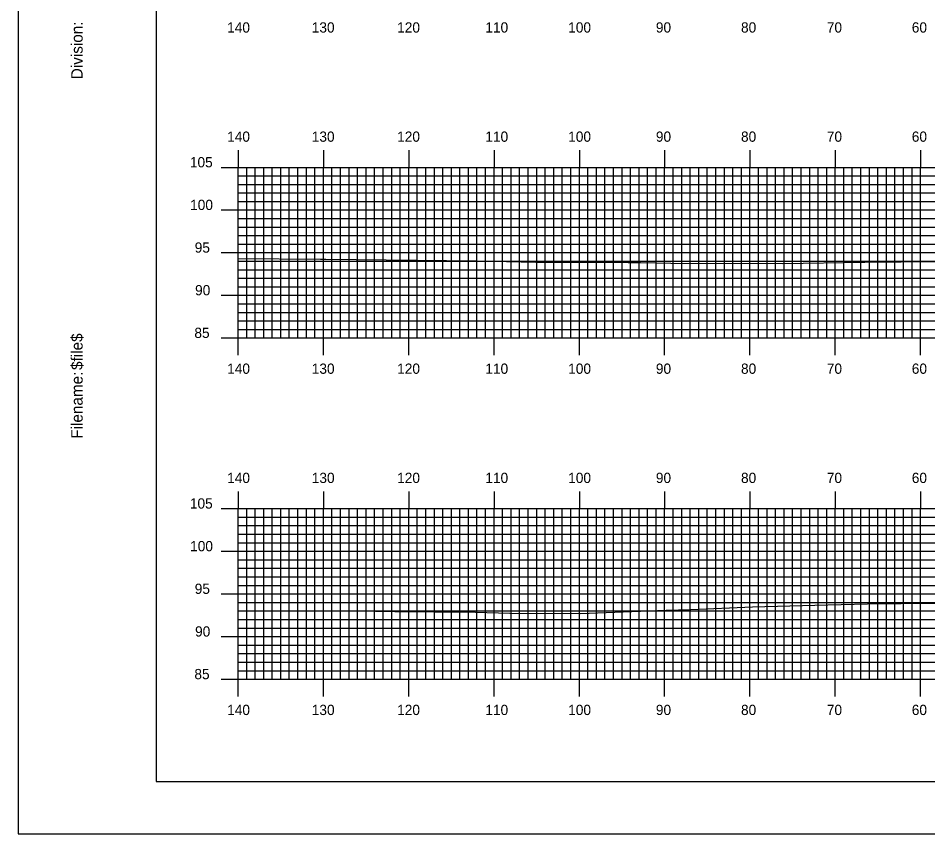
# Model space of a CAD drawing. Extents: x 1764152 to 1764495, y 442591 to 442811.
# Drawn here: x 1764152 to 1764258.7, y 442590.5 to 442686.2 of the extents above; entities that cross this region are included whole.
import ezdxf

# ---------------------------------------------------------------- set-up
doc = ezdxf.new("R2010")
doc.units = 0
for name, color, linetype in [('BORDER', 7, 'Continuous'), ('H_V ANNOTATION', 7, 'Continuous'), ('MAJOR', 7, 'Continuous'), ('MINOR', 7, 'Continuous'), ('PLOT BOUNDARY', 7, 'Continuous'), ('S_Roadway_Centerline', 7, 'Continuous')]:
    doc.layers.add(name, color=color, linetype=linetype)

msp = doc.modelspace()

# ---------------------------------------------------------------- linework, layer by layer
at = {"layer": 'BORDER'}
msp.add_lwpolyline([(1764168.23, 442596.67), (1764488.23, 442596.67), (1764488.23, 442806.67), (1764168.23, 442806.67)], close=True, dxfattribs=at)
at = {"layer": 'MAJOR'}
for p, q in [((1764177.83, 442670.67), (1764177.83, 442668.67)), ((1764187.83, 442670.67), (1764187.83, 442668.67)), ((1764197.83, 442670.67), (1764197.83, 442668.67)), ((1764207.83, 442670.67), (1764207.83, 442668.67)), ((1764217.83, 442670.67), (1764217.83, 442668.67)), ((1764227.83, 442670.67), (1764227.83, 442668.67)), ((1764237.83, 442670.67), (1764237.83, 442668.67)), ((1764247.83, 442670.67), (1764247.83, 442668.67)), ((1764257.83, 442670.67), (1764257.83, 442668.67)), ((1764175.83, 442668.67), (1764177.83, 442668.67)), ((1764177.83, 442668.67), (1764457.83, 442668.67)), ((1764177.83, 442648.67), (1764177.83, 442668.67)), ((1764177.83, 442648.67), (1764177.83, 442668.67)), ((1764177.83, 442668.67), (1764457.83, 442668.67)), ((1764187.83, 442648.67), (1764187.83, 442668.67)), ((1764197.83, 442648.67), (1764197.83, 442668.67)), ((1764207.83, 442648.67), (1764207.83, 442668.67)), ((1764217.83, 442648.67), (1764217.83, 442668.67)), ((1764227.83, 442648.67), (1764227.83, 442668.67)), ((1764237.83, 442648.67), (1764237.83, 442668.67)), ((1764247.83, 442648.67), (1764247.83, 442668.67)), ((1764257.83, 442648.67), (1764257.83, 442668.67)), ((1764175.83, 442663.67), (1764177.83, 442663.67)), ((1764177.83, 442663.67), (1764457.83, 442663.67)), ((1764175.83, 442658.67), (1764177.83, 442658.67)), ((1764177.83, 442658.67), (1764457.83, 442658.67)), ((1764175.83, 442653.67), (1764177.83, 442653.67)), ((1764177.83, 442653.67), (1764457.83, 442653.67)), ((1764175.83, 442648.67), (1764177.83, 442648.67)), ((1764177.83, 442648.67), (1764457.83, 442648.67)), ((1764177.83, 442648.67), (1764457.83, 442648.67)), ((1764177.83, 442646.66), (1764177.83, 442648.67)), ((1764187.83, 442646.66), (1764187.83, 442648.67)), ((1764197.83, 442646.66), (1764197.83, 442648.67)), ((1764207.83, 442646.66), (1764207.83, 442648.67)), ((1764217.83, 442646.66), (1764217.83, 442648.67)), ((1764227.83, 442646.66), (1764227.83, 442648.67)), ((1764237.83, 442646.66), (1764237.83, 442648.67)), ((1764247.83, 442646.66), (1764247.83, 442648.67)), ((1764257.83, 442646.66), (1764257.83, 442648.67)), ((1764177.83, 442630.67), (1764177.83, 442628.67)), ((1764187.83, 442630.67), (1764187.83, 442628.67)), ((1764197.83, 442630.67), (1764197.83, 442628.67)), ((1764207.83, 442630.67), (1764207.83, 442628.67)), ((1764217.83, 442630.67), (1764217.83, 442628.67)), ((1764227.83, 442630.67), (1764227.83, 442628.67)), ((1764237.83, 442630.67), (1764237.83, 442628.67)), ((1764247.83, 442630.67), (1764247.83, 442628.67)), ((1764257.83, 442630.67), (1764257.83, 442628.67)), ((1764175.83, 442628.67), (1764177.83, 442628.67)), ((1764177.83, 442628.67), (1764457.83, 442628.67)), ((1764177.83, 442608.67), (1764177.83, 442628.67)), ((1764177.83, 442608.67), (1764177.83, 442628.67)), ((1764177.83, 442628.67), (1764457.83, 442628.67)), ((1764187.83, 442608.67), (1764187.83, 442628.67)), ((1764197.83, 442608.67), (1764197.83, 442628.67)), ((1764207.83, 442608.67), (1764207.83, 442628.67)), ((1764217.83, 442608.67), (1764217.83, 442628.67)), ((1764227.83, 442608.67), (1764227.83, 442628.67)), ((1764237.83, 442608.67), (1764237.83, 442628.67)), ((1764247.83, 442608.67), (1764247.83, 442628.67)), ((1764257.83, 442608.67), (1764257.83, 442628.67)), ((1764175.83, 442623.67), (1764177.83, 442623.67)), ((1764177.83, 442623.67), (1764457.83, 442623.67)), ((1764175.83, 442618.67), (1764177.83, 442618.67)), ((1764177.83, 442618.67), (1764457.83, 442618.67)), ((1764175.83, 442613.67), (1764177.83, 442613.67)), ((1764177.83, 442613.67), (1764457.83, 442613.67)), ((1764175.83, 442608.67), (1764177.83, 442608.67)), ((1764177.83, 442608.67), (1764457.83, 442608.67)), ((1764177.83, 442608.67), (1764457.83, 442608.67)), ((1764177.83, 442606.66), (1764177.83, 442608.67)), ((1764187.83, 442606.66), (1764187.83, 442608.67)), ((1764197.83, 442606.66), (1764197.83, 442608.67)), ((1764207.83, 442606.66), (1764207.83, 442608.67)), ((1764217.83, 442606.66), (1764217.83, 442608.67)), ((1764227.83, 442606.66), (1764227.83, 442608.67)), ((1764237.83, 442606.66), (1764237.83, 442608.67)), ((1764247.83, 442606.66), (1764247.83, 442608.67)), ((1764257.83, 442606.66), (1764257.83, 442608.67))]:
    msp.add_line(p, q, dxfattribs=at)
at = {"layer": 'MINOR'}
for p, q in [((1764178.83, 442648.67), (1764178.83, 442668.67)), ((1764179.83, 442648.67), (1764179.83, 442668.67)), ((1764180.83, 442648.67), (1764180.83, 442668.67)), ((1764181.83, 442648.67), (1764181.83, 442668.67)), ((1764182.83, 442648.67), (1764182.83, 442668.67)), ((1764183.83, 442648.67), (1764183.83, 442668.67)), ((1764184.83, 442648.67), (1764184.83, 442668.67)), ((1764185.83, 442648.67), (1764185.83, 442668.67)), ((1764186.83, 442648.67), (1764186.83, 442668.67)), ((1764188.83, 442648.67), (1764188.83, 442668.67)), ((1764189.83, 442648.67), (1764189.83, 442668.67)), ((1764190.83, 442648.67), (1764190.83, 442668.67)), ((1764191.83, 442648.67), (1764191.83, 442668.67)), ((1764192.83, 442648.67), (1764192.83, 442668.67)), ((1764193.83, 442648.67), (1764193.83, 442668.67)), ((1764194.83, 442648.67), (1764194.83, 442668.67)), ((1764195.83, 442648.67), (1764195.83, 442668.67)), ((1764196.83, 442648.67), (1764196.83, 442668.67)), ((1764198.83, 442648.67), (1764198.83, 442668.67)), ((1764199.83, 442648.67), (1764199.83, 442668.67)), ((1764200.83, 442648.67), (1764200.83, 442668.67)), ((1764201.83, 442648.67), (1764201.83, 442668.67)), ((1764202.83, 442648.67), (1764202.83, 442668.67)), ((1764203.83, 442648.67), (1764203.83, 442668.67)), ((1764204.83, 442648.67), (1764204.83, 442668.67)), ((1764205.83, 442648.67), (1764205.83, 442668.67)), ((1764206.83, 442648.67), (1764206.83, 442668.67)), ((1764208.83, 442648.67), (1764208.83, 442668.67)), ((1764209.83, 442648.67), (1764209.83, 442668.67)), ((1764210.83, 442648.67), (1764210.83, 442668.67)), ((1764211.83, 442648.67), (1764211.83, 442668.67)), ((1764212.83, 442648.67), (1764212.83, 442668.67)), ((1764213.83, 442648.67), (1764213.83, 442668.67)), ((1764214.83, 442648.67), (1764214.83, 442668.67)), ((1764215.83, 442648.67), (1764215.83, 442668.67)), ((1764216.83, 442648.67), (1764216.83, 442668.67)), ((1764218.83, 442648.67), (1764218.83, 442668.67)), ((1764219.83, 442648.67), (1764219.83, 442668.67)), ((1764220.83, 442648.67), (1764220.83, 442668.67)), ((1764221.83, 442648.67), (1764221.83, 442668.67)), ((1764222.83, 442648.67), (1764222.83, 442668.67)), ((1764223.83, 442648.67), (1764223.83, 442668.67)), ((1764224.83, 442648.67), (1764224.83, 442668.67)), ((1764225.83, 442648.67), (1764225.83, 442668.67)), ((1764226.83, 442648.67), (1764226.83, 442668.67)), ((1764228.83, 442648.67), (1764228.83, 442668.67)), ((1764229.83, 442648.67), (1764229.83, 442668.67)), ((1764230.83, 442648.67), (1764230.83, 442668.67)), ((1764231.83, 442648.67), (1764231.83, 442668.67)), ((1764232.83, 442648.67), (1764232.83, 442668.67)), ((1764233.83, 442648.67), (1764233.83, 442668.67)), ((1764234.83, 442648.67), (1764234.83, 442668.67)), ((1764235.83, 442648.67), (1764235.83, 442668.67)), ((1764236.83, 442648.67), (1764236.83, 442668.67)), ((1764238.83, 442648.67), (1764238.83, 442668.67)), ((1764239.83, 442648.67), (1764239.83, 442668.67)), ((1764240.83, 442648.67), (1764240.83, 442668.67)), ((1764241.83, 442648.67), (1764241.83, 442668.67)), ((1764242.83, 442648.67), (1764242.83, 442668.67)), ((1764243.83, 442648.67), (1764243.83, 442668.67)), ((1764244.83, 442648.67), (1764244.83, 442668.67)), ((1764245.83, 442648.67), (1764245.83, 442668.67)), ((1764246.83, 442648.67), (1764246.83, 442668.67)), ((1764248.83, 442648.67), (1764248.83, 442668.67)), ((1764249.83, 442648.67), (1764249.83, 442668.67)), ((1764250.83, 442648.67), (1764250.83, 442668.67)), ((1764251.83, 442648.67), (1764251.83, 442668.67)), ((1764252.83, 442648.67), (1764252.83, 442668.67)), ((1764253.83, 442648.67), (1764253.83, 442668.67)), ((1764254.83, 442648.67), (1764254.83, 442668.67)), ((1764255.83, 442648.67), (1764255.83, 442668.67)), ((1764256.83, 442648.67), (1764256.83, 442668.67)), ((1764177.83, 442667.67), (1764457.83, 442667.67)), ((1764177.83, 442667.67), (1764179.84, 442667.67)), ((1764177.83, 442666.67), (1764457.83, 442666.67)), ((1764177.83, 442666.67), (1764179.84, 442666.67)), ((1764177.83, 442665.67), (1764457.83, 442665.67)), ((1764177.83, 442665.67), (1764179.84, 442665.67)), ((1764177.83, 442664.67), (1764457.83, 442664.67)), ((1764177.83, 442664.67), (1764179.84, 442664.67)), ((1764177.83, 442662.67), (1764457.83, 442662.67)), ((1764177.83, 442662.67), (1764179.84, 442662.67)), ((1764177.83, 442661.67), (1764457.83, 442661.67)), ((1764177.83, 442661.67), (1764179.84, 442661.67)), ((1764177.83, 442660.67), (1764457.83, 442660.67)), ((1764177.83, 442660.67), (1764179.84, 442660.67)), ((1764177.83, 442659.67), (1764457.83, 442659.67)), ((1764177.83, 442659.67), (1764179.84, 442659.67)), ((1764177.83, 442657.67), (1764457.83, 442657.67)), ((1764177.83, 442657.67), (1764179.84, 442657.67)), ((1764177.83, 442656.67), (1764457.83, 442656.67)), ((1764177.83, 442656.67), (1764179.84, 442656.67)), ((1764177.83, 442655.67), (1764457.83, 442655.67)), ((1764177.83, 442655.67), (1764179.84, 442655.67)), ((1764177.83, 442654.67), (1764457.83, 442654.67)), ((1764177.83, 442654.67), (1764179.84, 442654.67)), ((1764177.83, 442652.67), (1764457.83, 442652.67)), ((1764177.83, 442652.67), (1764179.84, 442652.67)), ((1764177.83, 442651.67), (1764457.83, 442651.67)), ((1764177.83, 442651.67), (1764179.84, 442651.67)), ((1764177.83, 442650.67), (1764457.83, 442650.67)), ((1764177.83, 442650.67), (1764179.84, 442650.67)), ((1764177.83, 442649.67), (1764457.83, 442649.67)), ((1764177.83, 442649.67), (1764179.84, 442649.67)), ((1764178.83, 442608.67), (1764178.83, 442628.67)), ((1764179.83, 442608.67), (1764179.83, 442628.67)), ((1764180.83, 442608.67), (1764180.83, 442628.67)), ((1764181.83, 442608.67), (1764181.83, 442628.67)), ((1764182.83, 442608.67), (1764182.83, 442628.67)), ((1764183.83, 442608.67), (1764183.83, 442628.67)), ((1764184.83, 442608.67), (1764184.83, 442628.67)), ((1764185.83, 442608.67), (1764185.83, 442628.67)), ((1764186.83, 442608.67), (1764186.83, 442628.67)), ((1764188.83, 442608.67), (1764188.83, 442628.67)), ((1764189.83, 442608.67), (1764189.83, 442628.67)), ((1764190.83, 442608.67), (1764190.83, 442628.67)), ((1764191.83, 442608.67), (1764191.83, 442628.67)), ((1764192.83, 442608.67), (1764192.83, 442628.67)), ((1764193.83, 442608.67), (1764193.83, 442628.67)), ((1764194.83, 442608.67), (1764194.83, 442628.67)), ((1764195.83, 442608.67), (1764195.83, 442628.67)), ((1764196.83, 442608.67), (1764196.83, 442628.67)), ((1764198.83, 442608.67), (1764198.83, 442628.67)), ((1764199.83, 442608.67), (1764199.83, 442628.67)), ((1764200.83, 442608.67), (1764200.83, 442628.67)), ((1764201.83, 442608.67), (1764201.83, 442628.67)), ((1764202.83, 442608.67), (1764202.83, 442628.67)), ((1764203.83, 442608.67), (1764203.83, 442628.67)), ((1764204.83, 442608.67), (1764204.83, 442628.67)), ((1764205.83, 442608.67), (1764205.83, 442628.67)), ((1764206.83, 442608.67), (1764206.83, 442628.67)), ((1764208.83, 442608.67), (1764208.83, 442628.67)), ((1764209.83, 442608.67), (1764209.83, 442628.67)), ((1764210.83, 442608.67), (1764210.83, 442628.67)), ((1764211.83, 442608.67), (1764211.83, 442628.67)), ((1764212.83, 442608.67), (1764212.83, 442628.67)), ((1764213.83, 442608.67), (1764213.83, 442628.67)), ((1764214.83, 442608.67), (1764214.83, 442628.67)), ((1764215.83, 442608.67), (1764215.83, 442628.67)), ((1764216.83, 442608.67), (1764216.83, 442628.67)), ((1764218.83, 442608.67), (1764218.83, 442628.67)), ((1764219.83, 442608.67), (1764219.83, 442628.67)), ((1764220.83, 442608.67), (1764220.83, 442628.67)), ((1764221.83, 442608.67), (1764221.83, 442628.67)), ((1764222.83, 442608.67), (1764222.83, 442628.67)), ((1764223.83, 442608.67), (1764223.83, 442628.67)), ((1764224.83, 442608.67), (1764224.83, 442628.67)), ((1764225.83, 442608.67), (1764225.83, 442628.67)), ((1764226.83, 442608.67), (1764226.83, 442628.67)), ((1764228.83, 442608.67), (1764228.83, 442628.67)), ((1764229.83, 442608.67), (1764229.83, 442628.67)), ((1764230.83, 442608.67), (1764230.83, 442628.67)), ((1764231.83, 442608.67), (1764231.83, 442628.67)), ((1764232.83, 442608.67), (1764232.83, 442628.67)), ((1764233.83, 442608.67), (1764233.83, 442628.67)), ((1764234.83, 442608.67), (1764234.83, 442628.67)), ((1764235.83, 442608.67), (1764235.83, 442628.67)), ((1764236.83, 442608.67), (1764236.83, 442628.67)), ((1764238.83, 442608.67), (1764238.83, 442628.67)), ((1764239.83, 442608.67), (1764239.83, 442628.67)), ((1764240.83, 442608.67), (1764240.83, 442628.67)), ((1764241.83, 442608.67), (1764241.83, 442628.67)), ((1764242.83, 442608.67), (1764242.83, 442628.67)), ((1764243.83, 442608.67), (1764243.83, 442628.67)), ((1764244.83, 442608.67), (1764244.83, 442628.67)), ((1764245.83, 442608.67), (1764245.83, 442628.67)), ((1764246.83, 442608.67), (1764246.83, 442628.67)), ((1764248.83, 442608.67), (1764248.83, 442628.67)), ((1764249.83, 442608.67), (1764249.83, 442628.67)), ((1764250.83, 442608.67), (1764250.83, 442628.67)), ((1764251.83, 442608.67), (1764251.83, 442628.67)), ((1764252.83, 442608.67), (1764252.83, 442628.67)), ((1764253.83, 442608.67), (1764253.83, 442628.67)), ((1764254.83, 442608.67), (1764254.83, 442628.67)), ((1764255.83, 442608.67), (1764255.83, 442628.67)), ((1764256.83, 442608.67), (1764256.83, 442628.67)), ((1764177.83, 442627.67), (1764457.83, 442627.67)), ((1764177.83, 442627.67), (1764179.84, 442627.67)), ((1764177.83, 442626.67), (1764457.83, 442626.67)), ((1764177.83, 442626.67), (1764179.84, 442626.67)), ((1764177.83, 442625.67), (1764457.83, 442625.67)), ((1764177.83, 442625.67), (1764179.84, 442625.67)), ((1764177.83, 442624.67), (1764457.83, 442624.67)), ((1764177.83, 442624.67), (1764179.84, 442624.67)), ((1764177.83, 442622.67), (1764457.83, 442622.67)), ((1764177.83, 442622.67), (1764179.84, 442622.67)), ((1764177.83, 442621.67), (1764457.83, 442621.67)), ((1764177.83, 442621.67), (1764179.84, 442621.67)), ((1764177.83, 442620.67), (1764457.83, 442620.67)), ((1764177.83, 442620.67), (1764179.84, 442620.67)), ((1764177.83, 442619.67), (1764457.83, 442619.67)), ((1764177.83, 442619.67), (1764179.84, 442619.67)), ((1764177.83, 442617.67), (1764457.83, 442617.67)), ((1764177.83, 442617.67), (1764179.84, 442617.67)), ((1764177.83, 442616.67), (1764457.83, 442616.67)), ((1764177.83, 442616.67), (1764179.84, 442616.67)), ((1764177.83, 442615.67), (1764457.83, 442615.67)), ((1764177.83, 442615.67), (1764179.84, 442615.67)), ((1764177.83, 442614.67), (1764457.83, 442614.67)), ((1764177.83, 442614.67), (1764179.84, 442614.67)), ((1764177.83, 442612.67), (1764457.83, 442612.67)), ((1764177.83, 442612.67), (1764179.84, 442612.67)), ((1764177.83, 442611.67), (1764457.83, 442611.67)), ((1764177.83, 442611.67), (1764179.84, 442611.67)), ((1764177.83, 442610.67), (1764457.83, 442610.67)), ((1764177.83, 442610.67), (1764179.84, 442610.67)), ((1764177.83, 442609.67), (1764457.83, 442609.67)), ((1764177.83, 442609.67), (1764179.84, 442609.67))]:
    msp.add_line(p, q, dxfattribs=at)
at = {"layer": 'PLOT BOUNDARY'}
msp.add_lwpolyline([(1764152.04, 442590.55), (1764492.04, 442590.55), (1764492.04, 442810.55), (1764152.04, 442810.55)], close=True, dxfattribs=at)
at = {"layer": 'S_Roadway_Centerline'}
for points in [[(1764177.83, 442657.97), (1764187.47, 442657.92), (1764187.83, 442657.92), (1764188.12, 442657.91), (1764205.8, 442657.71), (1764212.74, 442657.55), (1764223.56, 442657.51), (1764225, 442657.52), (1764228.54, 442657.44), (1764241.64, 442657.39), (1764251.28, 442657.55), (1764259.85, 442657.65)], [(1764177.83, 442616.65), (1764188.19, 442616.67), (1764191.62, 442616.67), (1764196.19, 442616.61), (1764205.64, 442616.52), (1764209.68, 442616.42), (1764217.96, 442616.39), (1764227.99, 442616.77), (1764230.91, 442616.85), (1764238.13, 442617.16), (1764245.45, 442617.35), (1764251.62, 442617.49), (1764263.46, 442617.61)]]:
    msp.add_lwpolyline(points, dxfattribs=at)

# ---------------------------------------------------------------- texts
at = {"layer": 'BORDER'}
for s, p in [('Division:', (1764159.6, 442679)), ('$file$', (1764159.6, 442644.92)), ('Filename:', (1764159.6, 442636.86))]:
    msp.add_text(s, height=1.339, rotation=90, dxfattribs=at).set_placement(p)
at = {"layer": 'H_V ANNOTATION'}
for s, p in [('140', (1764176.54, 442684.47)), ('130', (1764186.46, 442684.47)), ('120', (1764196.47, 442684.47)), ('110', (1764206.81, 442684.47)), ('100', (1764216.52, 442684.47)), ('90', (1764226.8, 442684.47)), ('80', (1764236.78, 442684.47)), ('70', (1764246.84, 442684.47)), ('60', (1764256.8, 442684.47)), ('140', (1764176.54, 442671.67)), ('130', (1764186.46, 442671.67)), ('120', (1764196.47, 442671.67)), ('110', (1764206.81, 442671.67)), ('100', (1764216.52, 442671.67)), ('90', (1764226.8, 442671.67)), ('80', (1764236.78, 442671.67)), ('70', (1764246.84, 442671.67)), ('60', (1764256.8, 442671.67)), ('105', (1764172.17, 442668.67)), ('100', (1764172.2, 442663.67)), ('95', (1764172.74, 442658.67)), ('90', (1764172.78, 442653.67)), ('85', (1764172.7, 442648.67)), ('140', (1764176.54, 442644.47)), ('130', (1764186.46, 442644.47)), ('120', (1764196.47, 442644.47)), ('110', (1764206.81, 442644.47)), ('100', (1764216.52, 442644.47)), ('90', (1764226.8, 442644.47)), ('80', (1764236.78, 442644.47)), ('70', (1764246.84, 442644.47)), ('60', (1764256.8, 442644.47)), ('140', (1764176.54, 442631.67)), ('130', (1764186.46, 442631.67)), ('120', (1764196.47, 442631.67)), ('110', (1764206.81, 442631.67)), ('100', (1764216.52, 442631.67)), ('90', (1764226.8, 442631.67)), ('80', (1764236.78, 442631.67)), ('70', (1764246.84, 442631.67)), ('60', (1764256.8, 442631.67)), ('105', (1764172.17, 442628.67)), ('100', (1764172.2, 442623.67)), ('95', (1764172.74, 442618.67)), ('90', (1764172.78, 442613.67)), ('85', (1764172.7, 442608.67)), ('140', (1764176.54, 442604.47)), ('130', (1764186.46, 442604.47)), ('120', (1764196.47, 442604.47)), ('110', (1764206.81, 442604.47)), ('100', (1764216.52, 442604.47)), ('90', (1764226.8, 442604.47)), ('80', (1764236.78, 442604.47)), ('70', (1764246.84, 442604.47)), ('60', (1764256.8, 442604.47))]:
    msp.add_text(s, height=1.2, dxfattribs=at).set_placement(p)
at = {"layer": 'MAJOR'}
for p in [(1764177.82, 442648.67), (1764177.82, 442608.67)]:
    msp.add_text('-', height=0.012, dxfattribs=at).set_placement(p)

doc.saveas('drawing.dxf')
